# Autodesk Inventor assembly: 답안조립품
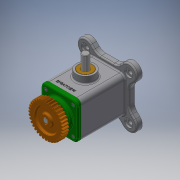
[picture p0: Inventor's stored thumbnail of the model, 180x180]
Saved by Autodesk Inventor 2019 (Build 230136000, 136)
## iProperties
Created: 2021-01
Part Number: 답안조립품
Material: 일반
Document SubType Name: Assembly
Designer: 3dpro6
Author: 3dpro6
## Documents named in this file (11)
- C:\Users\3dpro6\Desktop\710114V1002\답안조립품.iam
- C:\Users\3dpro6\Desktop\710114V1002\본체.ipt
- C:\Users\3dpro6\Desktop\710114V1002\볼트 M4.ipt
- C:\Users\3dpro6\Desktop\710114V1002\부시.ipt
- C:\Users\3dpro6\Desktop\710114V1002\스퍼기어.ipt
- C:\Users\3dpro6\Desktop\710114V1002\슬라이더.ipt
- C:\Users\3dpro6\Desktop\710114V1002\오일 실.ipt
- C:\Users\3dpro6\Desktop\710114V1002\커버.ipt
- C:\Users\3dpro6\Desktop\710114V1002\키 4 x 4 x 14.ipt
- C:\Users\3dpro6\Desktop\710114V1002\편심축.ipt
- C:\Users\3dpro6\Desktop\710114V1002\베어링 6203.ipt
